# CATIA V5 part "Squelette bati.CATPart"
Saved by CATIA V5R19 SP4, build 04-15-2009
Part number: Squelette bati
Bounding box of the stored display mesh (mm): x -500 to 500, y 100 to 1200, z -180 to 1800
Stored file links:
  G:\EU_thinkMotion\CFAO_2010\MMS_groupe1\MMS_groupe1\OK\rragonneau\rragonneau\Squelette bati.CATPart
  D:\Documents\Scolaire\MM2\CFAO\Brevet\MODELE CATIA\Squelette\Deambulateur.CATProduct
  G:\EU_thinkMotion\CFAO_2010\MMS_groupe1\MMS_groupe1\OK\rragonneau\rragonneau\squelette bras 1.CATPart
  G:\EU_thinkMotion\CFAO_2010\MMS_groupe1\MMS_groupe1\OK\rragonneau\rragonneau\squelette de base.CATPart
  G:\EU_thinkMotion\CFAO_2010\MMS_groupe1\MMS_groupe1\OK\rragonneau\rragonneau\squelette bras 2.CATPart
  G:\EU_thinkMotion\CFAO_2010\MMS_groupe1\MMS_groupe1\OK\rragonneau\rragonneau\Bras 2.CATPart
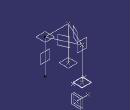
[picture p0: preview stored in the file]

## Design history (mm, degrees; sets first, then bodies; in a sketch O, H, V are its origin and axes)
External parameters (linked from other documents)
  `External.diam_moyeu_ext / epaisseur_bras&montant` = 60 mm
  External.largeur_siege = 500 mm
  External.profondeur_deamb = 1200 mm
  External.hauteur_deamb = 1800 mm
  External.diam_roue = 200 mm
Set1
  Line1: type PtPt, FirstPoint Point1, SecondPoint Point2
  Line2: type PtPt, FirstPoint Point3, SecondPoint Point4
  Line3: type PtPt, FirstPoint Point2, SecondPoint Point4
  Line4: type PtPt, FirstPoint Point2, SecondPoint Point5
  Line5: type PtPt, FirstPoint Point4, SecondPoint Point5
  Line6: type PtPt, FirstPoint Point5, SecondPoint Point6
  Plane1: type 2Lines, Element1 Line1, Element2 Line2
  Plane2: type OffsetPt, RefPlane Plane1, RefPoint Point5
  Plane3: type OffsetPt, RefPlane Plane10, RefPoint Point6
  Plane4: type OffsetPt, RefPlane Plane10, RefPoint Point2
  Plane5: type 2Lines, Element1 Line5, Element2 Line6
  Plane6: type 2Lines, Element1 Line4, Element2 Line6
  Plane7: type Offset, RefPlane Plane3, Offset -15 {= -`External.diam_moyeu_ext / epaisseur_bras&montant` /4}
  Line7: type PtPt, FirstPoint Point9, SecondPoint Point10
  Plane8: type Normal, Curve Line7, RefPoint Point10
  Plane9: type Offset, RefPlane Plane8, Offset 80 {= `External.diam_moyeu_ext / epaisseur_bras&montant` /2+External.diam_roue*1/4}, reversed
Set2
  Point1 to Point6: linked copy from another document
  Plane10: linked copy from another document
  Point7 to Point10: linked copy from another document
Body1 (main body)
